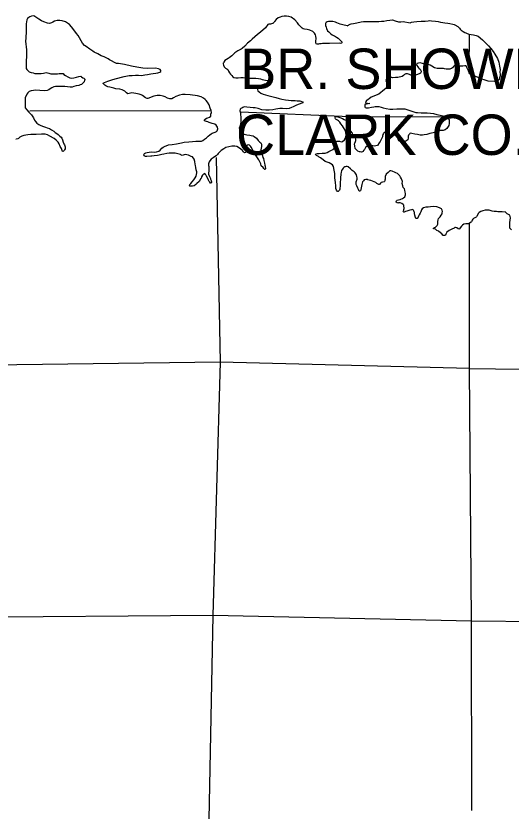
# Model space of a CAD drawing. Extents: x 369523 to 838377, y 495025 to 936819.
# Drawn here: x 559827 to 570168, y 800042 to 816667 of the extents above; entities that cross this region are included whole.
import ezdxf

# ---------------------------------------------------------------- set-up
doc = ezdxf.new("R2010")
doc.units = 0
for name, color, linetype in [('21', 7, 'Continuous'), ('Level 10', 7, 'Continuous'), ('Level 22', 7, 'Continuous')]:
    doc.layers.add(name, color=color, linetype=linetype)

msp = doc.modelspace()

# ---------------------------------------------------------------- linework, layer by layer
at = {"layer": 'Level 10'}
for points in [[(560304, 816599), (560198, 816667), (560156, 816661), (560120, 816647), (560094, 816632), (560067, 816610), (560055, 816584), (560045, 816542), (560043, 816500), (560043, 816460), (560043, 816396), (560042, 816348), (560038, 816296), (560036, 816248), (560032, 816194), (560030, 816148), (560033, 816066), (560039, 816024), (560045, 815950), (560049, 815906), (560049, 815868), (560046, 815804), (560042, 815744), (560042, 815705), (560038, 815655), (560038, 815599), (560044, 815567), (560055, 815543), (560075, 815527), (560097, 815503), (560107, 815498), (560143, 815486), (560185, 815478), (560225, 815466), (560273, 815462), (560318, 815460), (560358, 815464), (560404, 815473), (560458, 815481), (560488, 815475), (560518, 815467), (560554, 815459), (560618, 815457), (560658, 815459), (560696, 815458), (560732, 815460), (560768, 815464), (560792, 815466), (560812, 815460), (560830, 815444), (560862, 815420), (560912, 815390), (560954, 815374), (560996, 815367), (561036, 815369), (561092, 815387), (561138, 815401), (561182, 815405), (561200, 815395), (561226, 815375), (561246, 815362), (561264, 815344), (561266, 815332), (561262, 815320), (561250, 815291), (561232, 815269), (561218, 815253), (561196, 815235), (561170, 815223), (561140, 815215), (561086, 815205), (561038, 815193), (560999, 815180), (560963, 815178), (560903, 815182), (560851, 815190), (560765, 815194), (560651, 815193), (560617, 815185), (560575, 815163), (560545, 815139), (560515, 815119), (560478, 815109), (560416, 815102), (560328, 815110), (560240, 815112), (560148, 815099), (560106, 815085), (560076, 815061), (560052, 815031), (560023, 814951), (560019, 814929), (560019, 814881), (560017, 814833), (560017, 814781), (560021, 814747), (560023, 814743), (560056, 814703), (560094, 814655), (560114, 814639), (560150, 814599)], [(566746, 816461), (566654, 816478), (566598, 816494), (566566, 816508), (566530, 816522), (566500, 816534), (566474, 816541), (566446, 816547), (566414, 816551), (566390, 816551), (566354, 816547), (566324, 816541), (566309, 816531), (566301, 816521), (566293, 816507), (566289, 816495), (566291, 816475), (566295, 816463), (566303, 816429), (566311, 816403), (566337, 816357), (566361, 816331), (566383, 816311), (566407, 816289), (566435, 816269), (566459, 816257), (566481, 816247), (566499, 816239), (566525, 816223), (566557, 816201), (566577, 816181), (566593, 816168), (566605, 816154), (566618, 816140), (566626, 816130), (566632, 816124), (566634, 816112), (566634, 816104), (566624, 816096), (566608, 816091), (566582, 816095), (566374, 816091), (566284, 816092), (566232, 816088), (566204, 816086), (566168, 816082), (566146, 816076), (566116, 816074), (566098, 816086), (566094, 816112), (566094, 816142), (566096, 816196), (566088, 816244), (566082, 816270), (566064, 816306), (566026, 816344), (565964, 816371), (565912, 816383), (565856, 816389), (565824, 816399), (565802, 816411), (565782, 816429), (565737, 816479), (565711, 816519), (565655, 816582), (565575, 816638), (565529, 816652), (565475, 816664), (565431, 816664), (565383, 816654), (565345, 816643), (565306, 816629), (565260, 816595), (565228, 816551), (565218, 816535), (565206, 816523), (565192, 816511), (565188, 816509), (565144, 816497), (565108, 816496), (565086, 816488), (565039, 816420), (564937, 816324), (564869, 816277), (564816, 816229), (564762, 816179), (564724, 816143), (564666, 816094), (564605, 816032), (564549, 815984), (564533, 815974), (564459, 815936), (564399, 815893), (564374, 815867), (564336, 815829), (564284, 815793), (564260, 815775), (564222, 815753), (564192, 815732), (564170, 815702), (564160, 815686)], [(560944, 816489), (560862, 816543), (560792, 816567), (560744, 816571), (560690, 816571), (560634, 816558), (560596, 816538), (560572, 816522), (560532, 816506), (560486, 816514), (560412, 816540), (560364, 816561), (560304, 816599)], [(563765, 814494), (563777, 814510), (563805, 814526), (563833, 814534), (563873, 814552), (563901, 814574), (563897, 814610), (563911, 814650), (563902, 814686), (563886, 814738), (563864, 814806), (563830, 814860), (563802, 814896), (563776, 814922), (563746, 814946), (563698, 814974), (563618, 814996), (563466, 815017), (563364, 815025), (563304, 815021), (563240, 815010), (563168, 814982), (563121, 814954), (563083, 814936), (563039, 814934), (562993, 814949), (562947, 814973), (562899, 814987), (562843, 815001), (562775, 815003), (562707, 814990), (562653, 814970), (562603, 814944), (562583, 814940), (562567, 814938), (562533, 814956), (562473, 815002), (562441, 815018), (562403, 815031), (562333, 815045), (562251, 815059), (562193, 815043), (562166, 815041), (562137, 815058), (562105, 815090), (562049, 815122), (561997, 815134), (561915, 815140), (561869, 815154), (561790, 815175), (561748, 815181), (561708, 815203), (561684, 815221), (561665, 815237), (561649, 815253), (561647, 815261), (561679, 815277), (561745, 815299), (561831, 815330), (561897, 815354), (562086, 815403), (562190, 815419), (562256, 815423), (562322, 815429), (562390, 815426), (562448, 815424), (562518, 815434), (562575, 815442), (562643, 815457), (562695, 815465), (562749, 815473), (562791, 815479), (562831, 815493), (562853, 815507), (562855, 815525), (562841, 815543), (562807, 815557), (562739, 815573), (562571, 815568), (562479, 815574), (562349, 815598), (562239, 815619), (562093, 815649), (561973, 815672), (561926, 815672), (561779, 815748), (561753, 815770), (561669, 815813), (561605, 815835), (561539, 815873), (561463, 815907), (561431, 815929), (561373, 815969), (561293, 816024), (561263, 816048), (561219, 816098), (561124, 816254), (561094, 816296), (561038, 816374), (560990, 816436), (560944, 816489)], [(566746, 816461), (566805, 816495), (566825, 816498), (566880, 816509), (566946, 816523), (567035, 816544), (567089, 816553), (567231, 816551), (567292, 816551), (567342, 816550), (567404, 816550), (567462, 816555), (567510, 816559), (567572, 816570), (567637, 816578), (567691, 816584), (567745, 816563), (567814, 816541), (567866, 816540), (567916, 816550), (568060, 816524), (568090, 816533), (568136, 816540), (568197, 816547), (568287, 816554), (568323, 816557), (568375, 816558), (568434, 816564), (568474, 816569), (568506, 816566), (568590, 816560), (568645, 816550), (568697, 816537), (568745, 816529), (568787, 816522), (568847, 816513), (568887, 816506), (568950, 816494), (568976, 816485), (568992, 816483), (569022, 816468), (569028, 816460), (569055, 816443), (569079, 816426), (569090, 816410), (569104, 816392), (569127, 816371), (569165, 816344), (569200, 816323), (569222, 816313), (569240, 816304), (569285, 816283), (569335, 816277), (569385, 816274), (569437, 816259), (569482, 816241), (569574, 816167), (569695, 816042), (569747, 815982), (569792, 815921), (569830, 815866), (569884, 815773), (569914, 815698), (569928, 815616), (569940, 815543), (569936, 815494), (569937, 815448), (569940, 815412), (569929, 815372), (569916, 815334), (569902, 815321), (569879, 815311), (569815, 815293), (569691, 815301), (569603, 815329), (569556, 815344), (569482, 815376), (569435, 815399), (569383, 815417), (569336, 815434), (569310, 815455), (569295, 815477), (569278, 815518), (569267, 815546), (569252, 815576), (569236, 815607), (569217, 815623), (569199, 815622), (569161, 815617), (569141, 815615), (569091, 815617), (569059, 815626), (569027, 815636), (568991, 815635), (568966, 815612), (568947, 815579), (568927, 815565), (568903, 815560), (568887, 815556), (568836, 815554), (568810, 815555)], [(564160, 815686), (564157, 815676), (564155, 815664), (564163, 815638), (564177, 815602), (564205, 815576), (564235, 815558), (564253, 815549), (564267, 815515), (564289, 815479), (564309, 815449), (564333, 815421), (564357, 815393), (564381, 815379), (564417, 815369), (564467, 815375), (564523, 815381), (564571, 815382), (564637, 815374), (564703, 815366), (564763, 815366), (564805, 815368), (564839, 815364), (564891, 815359), (564935, 815351), (564967, 815335), (565077, 815317), (565111, 815305), (565135, 815289), (565145, 815273), (565141, 815259), (565099, 815245), (565055, 815247), (565015, 815239), (564979, 815227), (564949, 815209), (564889, 815186), (564871, 815176), (564871, 815166), (564869, 815148), (564872, 815130), (564882, 815098), (564904, 815080), (564944, 815053), (564990, 815033), (565090, 815003), (565256, 814958), (565324, 814940), (565378, 814926), (565456, 814914), (565522, 814903), (565573, 814899), (565657, 814895), (565699, 814891), (565731, 814891), (565757, 814889), (565777, 814887), (565813, 814870), (565823, 814852), (565819, 814850), (565722, 814815), (565672, 814793), (565616, 814767), (565580, 814751), (565534, 814732), (565476, 814724), (565396, 814732), (565340, 814734), (565257, 814719), (565193, 814701), (565119, 814693), (565043, 814693), (564963, 814706), (564885, 814730), (564821, 814742), (564781, 814748), (564717, 814751), (564651, 814757), (564605, 814763), (564583, 814759), (564567, 814753), (564545, 814741), (564525, 814729), (564512, 814715), (564506, 814685), (564512, 814663), (564516, 814637), (564520, 814597), (564524, 814557), (564524, 814529), (564526, 814497), (564524, 814465), (564515, 814398), (564503, 814354), (564489, 814320), (564493, 814290), (564499, 814258), (564505, 814236), (564513, 814218), (564535, 814198), (564575, 814198)], [(568810, 815555), (568780, 815559), (568755, 815564), (568723, 815569), (568687, 815568), (568663, 815567), (568643, 815569), (568623, 815570), (568595, 815576), (568571, 815583), (568516, 815613), (568480, 815640), (568437, 815653), (568393, 815660), (568367, 815665), (568315, 815674), (568267, 815683), (568201, 815673), (568199, 815671), (568192, 815641), (568198, 815629), (568221, 815599), (568236, 815582), (568250, 815566), (568266, 815551), (568287, 815513), (568288, 815497), (568286, 815487), (568275, 815473), (568265, 815460), (568216, 815439), (568174, 815428), (568122, 815426), (568104, 815426), (568086, 815427), (568076, 815429), (568048, 815444), (568029, 815452), (568007, 815457), (567971, 815456), (567942, 815443), (567918, 815423), (567893, 815400), (567869, 815391), (567828, 815386), (567800, 815380), (567756, 815376), (567702, 815375), (567680, 815378), (567662, 815382), (567612, 815382), (567592, 815376), (567579, 815363), (567569, 815349), (567550, 815317), (567556, 815295), (567571, 815277), (567585, 815264), (567594, 815250), (567596, 815236), (567597, 815190), (567588, 815164), (567562, 815153), (567525, 815130), (567404, 815032), (567248, 814970), (567207, 814935), (567183, 814918), (567154, 814899), (567152, 814897), (567136, 814879), (567125, 814851), (567217, 814837), (567114, 814816), (567113, 814786), (567115, 814768), (567124, 814752), (567140, 814743), (567188, 814748), (567255, 814762), (567301, 814769), (567331, 814772), (567405, 814770), (567455, 814762), (567498, 814747), (567562, 814734), (567636, 814720), (567698, 814716), (567780, 814722), (567814, 814725), (567946, 814723), (568032, 814697), (568181, 814649), (568217, 814644), (568291, 814640), (568365, 814640), (568417, 814638), (568483, 814634), (568551, 814624), (568618, 814609), (568690, 814589)], [(560150, 814599), (560168, 814577), (560180, 814559), (560194, 814535), (560216, 814485), (560236, 814457), (560264, 814427), (560306, 814397), (560348, 814375), (560400, 814356), (560446, 814342), (560480, 814328), (560526, 814310), (560570, 814284), (560616, 814254), (560648, 814232), (560681, 814208), (560711, 814187), (560743, 814155), (560769, 814129), (560783, 814109), (560799, 814077), (560813, 814029), (560831, 813993), (560841, 813971), (560849, 813953), (560853, 813927), (560855, 813913), (560853, 813889), (560844, 813867), (560834, 813851), (560824, 813839), (560804, 813831), (560800, 813831), (560788, 813871), (560778, 813893), (560751, 813940), (560729, 813992), (560709, 814024), (560669, 814070), (560629, 814102), (560537, 814156), (560487, 814178), (560439, 814194), (560363, 814191), (560249, 814187), (560197, 814187), (560141, 814186), (560077, 814180), (560036, 814174), (559992, 814168), (559950, 814154), (559912, 814134), (559880, 814103), (559866, 814095), (559834, 814087), (559824, 814095)], [(563771, 813371), (563771, 813373), (563748, 813361), (563726, 813339), (563704, 813299), (563694, 813270), (563692, 813268), (563652, 813208), (563608, 813160), (563585, 813142), (563549, 813116), (563515, 813106), (563491, 813106), (563469, 813106), (563457, 813107), (563449, 813117), (563459, 813140), (563477, 813164), (563508, 813196), (563542, 813238), (563574, 813282), (563594, 813318), (563602, 813388), (563602, 813406), (563595, 813452), (563583, 813500), (563577, 813536), (563571, 813568), (563565, 813622), (563551, 813670), (563517, 813718), (563485, 813728), (563430, 813758), (563365, 813766), (563321, 813752), (563297, 813751), (563271, 813761), (563263, 813767), (563211, 813785), (563153, 813795), (563095, 813797), (563025, 813797), (562979, 813790), (562913, 813776), (562877, 813766), (562821, 813754), (562781, 813750), (562716, 813741), (562664, 813737), (562648, 813735), (562560, 813731), (562536, 813731), (562504, 813743), (562502, 813765), (562504, 813775), (562512, 813787), (562524, 813797), (562540, 813803), (562567, 813811), (562613, 813819), (562665, 813823), (562721, 813821), (562765, 813828), (562809, 813840), (562837, 813862), (562877, 813904), (562899, 813924), (562928, 813940), (563012, 813969), (563092, 813979), (563182, 813993), (563282, 814010), (563340, 814026), (563435, 814036), (563517, 814043), (563587, 814045), (563657, 814047), (563703, 814051), (563729, 814063), (563769, 814087), (563807, 814118), (563844, 814156), (563874, 814180), (563904, 814202), (563928, 814216), (563964, 814228), (563990, 814236), (564014, 814253), (564032, 814267), (564044, 814307), (564036, 814343), (564011, 814381), (563983, 814401), (563925, 814420), (563887, 814432), (563865, 814440), (563837, 814450), (563807, 814456), (563785, 814464), (563769, 814476), (563765, 814494)], [(566814, 813467), (566763, 813512), (566745, 813516), (566721, 813518), (566703, 813514), (566697, 813510), (566675, 813495), (566661, 813483), (566645, 813461), (566629, 813435), (566620, 813395), (566616, 813365), (566606, 813275), (566604, 813237), (566598, 813199), (566598, 813169), (566597, 813103), (566595, 813069), (566595, 813047), (566587, 813025), (566559, 812995), (566553, 812993), (566537, 813003), (566525, 813024), (566511, 813060), (566507, 813117), (566500, 813187), (566496, 813235), (566488, 813283), (566484, 813329), (566484, 813371), (566476, 813445), (566457, 813519), (566439, 813553), (566407, 813577), (566367, 813596), (566329, 813608), (566283, 813624), (566245, 813656), (566219, 813678), (566189, 813698), (566163, 813714), (566143, 813728), (566121, 813740), (566103, 813750), (566087, 813770), (566091, 813784), (566117, 813792), (566161, 813792), (566221, 813794), (566257, 813796), (566288, 813800), (566324, 813814), (566362, 813835), (566420, 813861), (566452, 813875), (566484, 813917), (566498, 813949), (566513, 813999), (566517, 814019), (566523, 814043), (566531, 814049), (566549, 814049), (566583, 814046), (566621, 814034), (566649, 814040), (566687, 814074), (566709, 814112), (566723, 814176), (566718, 814236), (566706, 814280), (566670, 814336), (566646, 814368), (566616, 814412), (566590, 814442), (566564, 814470), (566540, 814486), (566514, 814502), (566500, 814518), (566492, 814530), (566490, 814538), (566492, 814546), (566495, 814554), (566511, 814562), (566551, 814554), (566591, 814544), (566645, 814524), (566681, 814504), (566699, 814496), (566717, 814484), (566737, 814459), (566758, 814429), (566792, 814311)], [(568690, 814589), (568750, 814579), (568795, 814568), (568809, 814559), (568841, 814535), (568856, 814524), (568875, 814492), (568877, 814460), (568877, 814414), (568870, 814376), (568824, 814311), (568794, 814282), (568749, 814273), (568681, 814271), (568661, 814264), (568614, 814239), (568540, 814223), (568473, 814211), (568449, 814202), (568406, 814187), (568352, 814180), (568320, 814177), (568266, 814175), (568212, 814184), (568156, 814194), (568097, 814211), (568069, 814214), (568055, 814210), (568044, 814197), (568030, 814183), (568025, 814171), (568021, 814151), (568020, 814115), (568009, 814076), (567994, 814060), (567968, 814049), (567928, 814044), (567892, 814035), (567850, 814038), (567822, 814055), (567814, 814069), (567809, 814083), (567811, 814105), (567810, 814125), (567812, 814135), (567809, 814155), (567807, 814179), (567806, 814187), (567804, 814199), (567790, 814204), (567778, 814204), (567762, 814201), (567719, 814186), (567703, 814174), (567693, 814162), (567686, 814153), (567674, 814143), (567662, 814135), (567650, 814134), (567642, 814140), (567627, 814158), (567607, 814173), (567574, 814212), (567562, 814230), (567547, 814238), (567531, 814239), (567522, 814231), (567514, 814223), (567502, 814210), (567493, 814188), (567484, 814154), (567480, 814140), (567461, 814095), (567448, 814067), (567435, 814042), (567416, 814012), (567381, 813959), (567342, 813950), (567310, 813947), (567282, 813948), (567252, 813955), (567227, 813967), (567219, 813970), (567189, 813968), (567187, 813967), (567181, 813965), (567162, 813943), (567129, 813914), (567106, 813875), (567094, 813859), (567069, 813834), (567063, 813824), (567042, 813821), (567019, 813823), (567005, 813824), (566971, 813837), (566961, 813843), (566940, 813867), (566914, 813898), (566913, 813902), (566906, 813944)], [(566906, 813944), (566901, 813994), (566905, 814006), (566916, 814038), (566923, 814062), (566924, 814092), (566920, 814116), (566913, 814130), (566895, 814152), (566880, 814163), (566866, 814181), (566853, 814212), (566841, 814232), (566830, 814252), (566811, 814275), (566792, 814311)], [(564575, 814198), (564597, 814193), (564651, 814181), (564715, 814173), (564741, 814167), (564773, 814161), (564783, 814157), (564805, 814147), (564853, 814109), (564887, 814061), (564922, 814026), (564940, 814012), (564954, 813988), (564956, 813950), (564954, 813938), (564950, 813902), (564944, 813870), (564944, 813864), (564950, 813818), (564958, 813788), (564974, 813738), (564987, 813708), (564995, 813688), (565005, 813646), (565011, 813614), (565017, 813586), (565025, 813548), (565031, 813524), (565035, 813508), (565039, 813494), (565039, 813478), (565031, 813455), (565027, 813457), (565005, 813479), (564991, 813495), (564947, 813535), (564945, 813573), (564899, 813659), (564845, 813739), (564829, 813765), (564804, 813809), (564778, 813857), (564742, 813923), (564724, 813945), (564702, 813963), (564674, 813969), (564658, 813963), (564650, 813959), (564642, 813939), (564630, 813900), (564635, 813848), (564631, 813818), (564621, 813808), (564601, 813802), (564579, 813828), (564561, 813850), (564523, 813884), (564493, 813902), (564440, 813936), (564397, 813944), (564335, 813941), (564277, 813933), (564213, 813915), (564169, 813889), (564113, 813853), (564079, 813818), (564054, 813788), (564038, 813768), (564008, 813742), (563972, 813720), (563944, 813702), (563906, 813672), (563876, 813635), (563862, 813615), (563847, 813575), (563851, 813539), (563857, 813517), (563855, 813481), (563853, 813445), (563851, 813363), (563851, 813361), (563870, 813309), (563890, 813269), (563894, 813253), (563904, 813225), (563908, 813217), (563914, 813201), (563914, 813191), (563912, 813183), (563908, 813179), (563900, 813173), (563892, 813171), (563878, 813189), (563866, 813207), (563852, 813233), (563836, 813269), (563810, 813315), (563796, 813341), (563787, 813351), (563773, 813371), (563771, 813371)], [(567932, 812661), (567930, 812677), (567931, 812689), (567925, 812709), (567912, 812724), (567886, 812744), (567850, 812757), (567836, 812758), (567815, 812760), (567804, 812755), (567786, 812761), (567767, 812776), (567769, 812788), (567776, 812801), (567788, 812813), (567820, 812824), (567850, 812831), (567867, 812837), (567899, 812850), (567922, 812865), (567946, 812887), (567961, 812926), (567962, 812952), (567959, 812982), (567948, 813026), (567939, 813049), (567927, 813063), (567919, 813069), (567915, 813079), (567904, 813112), (567896, 813162), (567903, 813205), (567880, 813262), (567861, 813293), (567842, 813321), (567793, 813370), (567762, 813387), (567732, 813402), (567700, 813413), (567688, 813419), (567657, 813430), (567651, 813430), (567639, 813427), (567630, 813421), (567599, 813390), (567559, 813357), (567537, 813307), (567536, 813270), (567538, 813255), (567533, 813232), (567529, 813220), (567522, 813206), (567516, 813200), (567492, 813189), (567480, 813193), (567458, 813186), (567441, 813172), (567421, 813145), (567404, 813141), (567365, 813166), (567341, 813181), (567308, 813200), (567274, 813213), (567238, 813224), (567205, 813233), (567177, 813243), (567173, 813244), (567137, 813247), (567103, 813237), (567086, 813220), (567067, 813195), (567057, 813167), (567054, 813139), (567045, 813107), (567038, 813071), (567031, 813038), (567020, 813012), (567002, 813000), (566996, 813005), (566979, 813039), (566970, 813063), (566949, 813112), (566936, 813140), (566934, 813162), (566935, 813196), (566955, 813254), (566954, 813282), (566946, 813308), (566937, 813344), (566928, 813364), (566912, 813383), (566893, 813405), (566873, 813418), (566850, 813436), (566838, 813449), (566830, 813455), (566814, 813467)], [(569534, 812577), (569503, 812560), (569491, 812542), (569455, 812479), (569449, 812466), (569436, 812456), (569386, 812429), (569369, 812416), (569357, 812398), (569350, 812378), (569344, 812365), (569336, 812355), (569280, 812318), (569272, 812317), (569236, 812320), (569222, 812322), (569180, 812313), (569151, 812290), (569133, 812268), (569108, 812233), (569093, 812212), (569075, 812208), (569061, 812217), (569032, 812233), (569010, 812240), (568990, 812240), (568980, 812229), (568933, 812208), (568872, 812178), (568829, 812149), (568819, 812135), (568806, 812106), (568799, 812086), (568781, 812078), (568767, 812073), (568751, 812075), (568720, 812108), (568697, 812131), (568651, 812164), (568618, 812183), (568604, 812193), (568590, 812205), (568559, 812214), (568551, 812215), (568551, 812227), (568561, 812238), (568569, 812242), (568588, 812251), (568602, 812261), (568625, 812282), (568637, 812312), (568638, 812344), (568637, 812372), (568644, 812400), (568653, 812430), (568684, 812465), (568711, 812504), (568727, 812531), (568730, 812549), (568735, 812579), (568730, 812609), (568714, 812634), (568671, 812655), (568619, 812674), (568553, 812684), (568485, 812676), (568435, 812669), (568391, 812665), (568338, 812652), (568312, 812631), (568299, 812611), (568284, 812572), (568271, 812542), (568248, 812507), (568235, 812481), (568225, 812459), (568204, 812432), (568194, 812430), (568182, 812432), (568171, 812453), (568158, 812501), (568151, 812539), (568149, 812555), (568144, 812571), (568140, 812592), (568129, 812606), (568105, 812618), (568085, 812613), (568053, 812604), (567994, 812584), (567960, 812578), (567937, 812567), (567929, 812563), (567925, 812567), (567919, 812570), (567916, 812582), (567920, 812590), (567927, 812609), (567931, 812621), (567935, 812639), (567932, 812661)], [(570176, 812192), (570145, 812231), (570140, 812271), (570144, 812345), (570159, 812448), (570141, 812499), (570089, 812532), (570060, 812559), (570056, 812561), (569982, 812571), (569960, 812569), (569924, 812568), (569894, 812571), (569866, 812576), (569834, 812577), (569816, 812581), (569774, 812585), (569709, 812608), (569675, 812609), (569629, 812605), (569580, 812592), (569534, 812577)]]:
    msp.add_lwpolyline(points, dxfattribs=at)
at = {"layer": 'Level 22'}
for points in [[(569294, 815564), (569299, 816273)], [(563900, 814680), (560118, 814673)], [(566800, 814558), (564526, 814655)], [(568779, 814550), (566800, 814558)], [(564006, 813704), (564093, 809429), (563941, 804133), (563832, 798802), (563820, 793471)], [(569346, 800058), (569342, 804011), (569299, 809297), (569300, 812326)], [(569299, 809297), (564093, 809429), (558779, 809361), (553358, 809312), (548925, 809508)], [(569299, 809297), (571474, 809268)], [(569342, 804011), (563941, 804133), (558622, 804090), (553313, 804107), (548857, 804231)], [(572198, 803986), (569342, 804011)]]:
    msp.add_lwpolyline(points, dxfattribs=at)

# ---------------------------------------------------------------- texts
at = {"layer": '21'}
for s, p in [('BR. SHOWN ON', (564510, 815139)), ('CLARK CO. LOG', (564426, 813760))]:
    msp.add_text(s, height=844.8, dxfattribs=at).set_placement(p)

doc.saveas('drawing.dxf')
